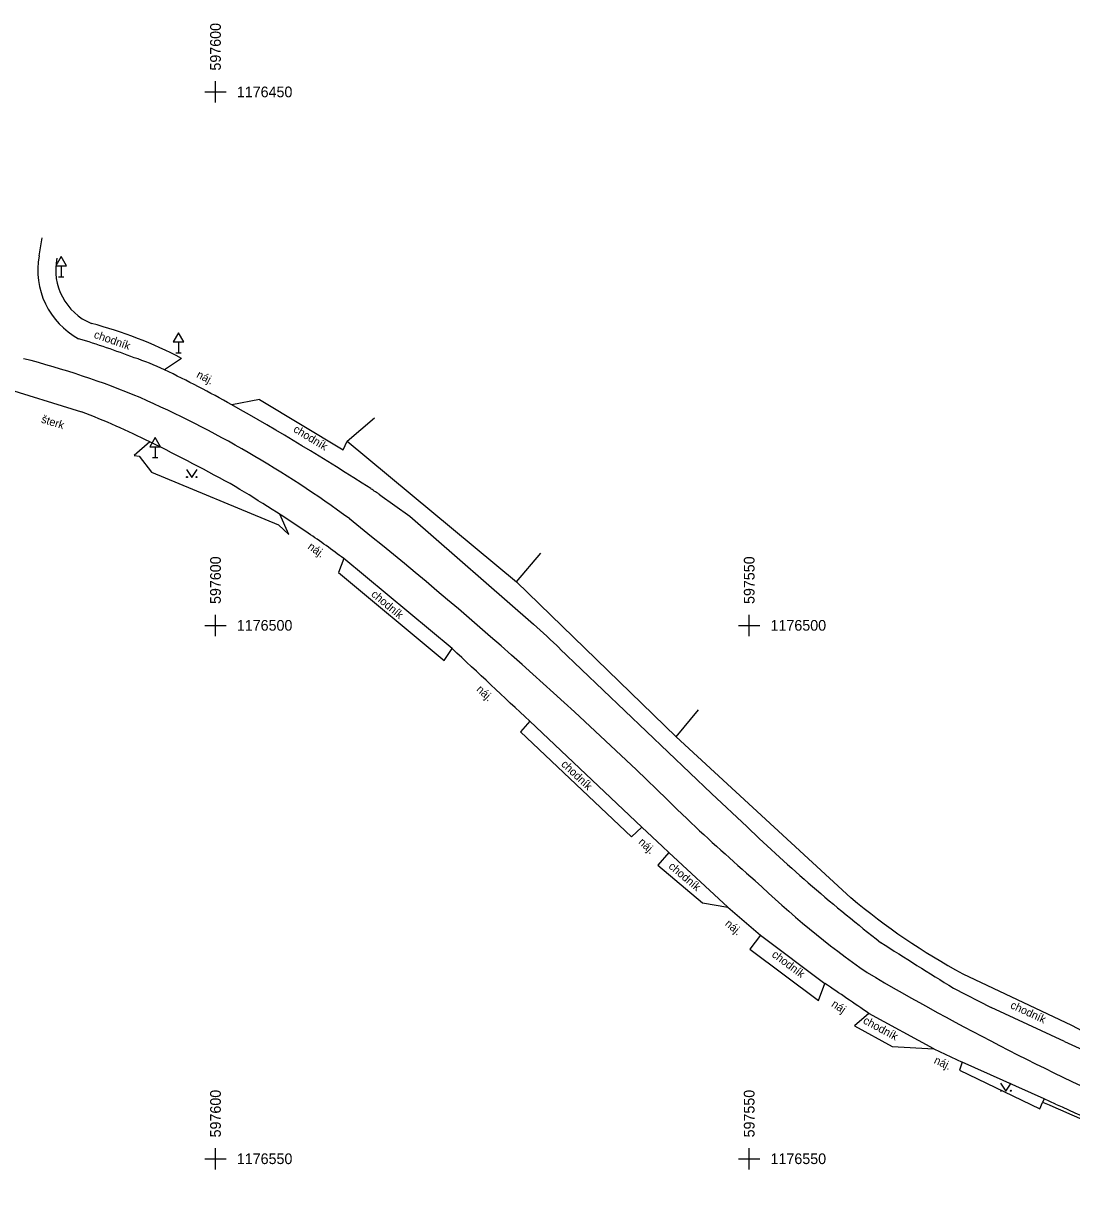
# Model space of a CAD drawing. Extents: x -598160 to -596067, y -1177005 to -1176344.
# Drawn here: x -597618 to -597519.8, y -1176553.9 to -1176443.6 of the extents above; entities that cross this region are included whole.
import ezdxf

# ---------------------------------------------------------------- set-up
doc = ezdxf.new("R2010")
doc.units = 0
for name, color, linetype in [('budova', 7, 'Continuous'), ('dopravní značení svislé', 7, 'Continuous'), ('hektametrová síť', 7, 'Continuous'), ('obruba +0 cm', 7, 'Continuous'), ('obruba +12 cm', 7, 'Continuous'), ('obruba +3 cm', 7, 'Continuous'), ('obruba +7 cm', 7, 'Continuous'), ('ohradní zeď', 7, 'Continuous'), ('plot', 7, 'Continuous'), ('popis ploch', 7, 'Continuous'), ('rozhraní ploch', 7, 'Continuous'), ('vodorovné značení', 7, 'Continuous'), ('zeleň', 7, 'Continuous')]:
    doc.layers.add(name, color=color, linetype=linetype)

msp = doc.modelspace()

# ---------------------------------------------------------------- linework, layer by layer
at = {"layer": 'budova'}
for p, q in [((-597587.65, -1176482.73), (-597585.09, -1176480.55)), ((-597587.65, -1176482.73), (-597571.8, -1176495.92)), ((-597571.8, -1176495.92), (-597569.52, -1176493.23)), ((-597571.8, -1176495.92), (-597556.83, -1176510.46)), ((-597556.83, -1176510.46), (-597554.74, -1176507.93))]:
    msp.add_line(p, q, dxfattribs=at)
at = {"layer": 'dopravní značení svislé'}
for p, q in [((-597614.45, -1176466.31), (-597614.45, -1176467.32)), ((-597614.7, -1176467.32), (-597614.2, -1176467.32)), ((-597603.72, -1176474.45), (-597603.22, -1176474.45)), ((-597603.47, -1176473.44), (-597603.47, -1176474.45)), ((-597605.64, -1176483.26), (-597605.64, -1176484.27)), ((-597605.89, -1176484.27), (-597605.39, -1176484.27))]:
    msp.add_line(p, q, dxfattribs=at)
for points in [[(-597614.95, -1176466.31), (-597613.95, -1176466.31), (-597614.45, -1176465.44)], [(-597603.97, -1176473.44), (-597602.97, -1176473.44), (-597603.47, -1176472.57)], [(-597606.14, -1176483.26), (-597605.14, -1176483.26), (-597605.64, -1176482.39)]]:
    msp.add_lwpolyline(points, close=True, dxfattribs=at)
at = {"layer": 'hektametrová síť'}
for p, q in [((-597600, -1176451), (-597600, -1176449)), ((-597601, -1176450), (-597599, -1176450)), ((-597600, -1176501), (-597600, -1176499)), ((-597550, -1176501), (-597550, -1176499)), ((-597601, -1176500), (-597599, -1176500)), ((-597551, -1176500), (-597549, -1176500)), ((-597600, -1176551), (-597600, -1176549)), ((-597550, -1176551), (-597550, -1176549)), ((-597601, -1176550), (-597599, -1176550)), ((-597551, -1176550), (-597549, -1176550))]:
    msp.add_line(p, q, dxfattribs=at)
at = {"layer": 'obruba +0 cm'}
for p, q in [((-597584.59, -1176487.76), (-597581.78, -1176489.77)), ((-597552.01, -1176526.42), (-597548.94, -1176529.05)), ((-597530.87, -1176534), (-597527.34, -1176535.81)), ((-597532.7, -1176539.69), (-597530.05, -1176540.95))]:
    msp.add_line(p, q, dxfattribs=at)
for centre, radius, start, end in [((-597660.89, -1176591.52), 128.39, 60.9119, 64.082), ((-597627.7, -1176545.57), 65.29, 52.5335, 56.1311), ((-597648.28, -1176586.93), 116.92, 46.4539, 48.1081), ((-597904.66, -1177067.79), 645.18, 55.45234, 55.89646), ((-597242.16, -1175937.85), 662.45, 245.15933, 245.4221)]:
    msp.add_arc(centre, radius, start, end, dxfattribs=at)
at = {"layer": 'obruba +12 cm'}
for p, q in [((-597616.51, -1176465.36), (-597616.25, -1176463.68)), ((-597577.83, -1176502.17), (-597587.98, -1176493.75)), ((-597570.56, -1176508.98), (-597560.06, -1176518.93)), ((-597557.52, -1176521.29), (-597552.01, -1176526.42)), ((-597548.94, -1176529.05), (-597542.92, -1176533.57)), ((-597520.45, -1176539.01), (-597527.34, -1176535.81)), ((-597532.7, -1176539.69), (-597538.79, -1176536.39)), ((-597522.38, -1176544.37), (-597530.05, -1176540.95)), ((-597521.29, -1176544.87), (-597522.38, -1176544.37))]:
    msp.add_line(p, q, dxfattribs=at)
for centre, radius, start, end in [((-597609.36, -1176466.73), 7.28, 169.1666, 241.6399), ((-597639.29, -1176558.95), 89.81, 69.3501, 72.857), ((-597615.72, -1176499.5), 25.89, 64.9776, 71.7667), ((-597637.42, -1176544.87), 69.49, 63.2593, 69.0318), ((-597736.09, -1176721.89), 278.89, 57.3045, 60.4323), ((-597687.62, -1176648.49), 184.63, 61.0122, 63.8136), ((-597673.07, -1176611.79), 145.56, 55.8283, 59.0236), ((-597669.94, -1176614.12), 152.48, 55.9624, 56.3461), ((-597439.97, -1176404.2), 159.07, 226.1417, 232.0993), ((-597282.83, -1176131.78), 472.55, 237.3635, 238.3388), ((-595960.58, -1173088.91), 3792.03, 245.69611, 246.01452)]:
    msp.add_arc(centre, radius, start, end, dxfattribs=at)
at = {"layer": 'obruba +3 cm'}
for p, q in [((-597620.23, -1176477.61), (-597612.55, -1176479.98)), ((-597553.53, -1176515.77), (-597550.18, -1176518.9)), ((-597560.06, -1176518.93), (-597558.13, -1176520.73)), ((-597558.13, -1176520.73), (-597557.52, -1176521.29))]:
    msp.add_line(p, q, dxfattribs=at)
msp.add_arc((-657799.42, -1240798.88), 88094.87, 46.8679742, 46.874453, dxfattribs=at)
at = {"layer": 'obruba +7 cm'}
for p, q in [((-597581.78, -1176489.77), (-597570.21, -1176499.9)), ((-597567.73, -1176502.19), (-597553.53, -1176515.77))]:
    msp.add_line(p, q, dxfattribs=at)
at = {"layer": 'ohradní zeď'}
msp.add_line((-597522.78, -1176545.31), (-597522.51, -1176544.72), dxfattribs=at)
msp.add_line((-597522.78, -1176545.31), (-597522.51, -1176544.72), dxfattribs=at)
msp.add_arc((-597741.74, -1177054.96), 555.35, 64.4531, 66.7485, dxfattribs=at)
at = {"layer": 'plot'}
msp.add_line((-597519.81, -1176537.49), (-597510, -1176542.72), dxfattribs=at)
at = {"layer": 'rozhraní ploch'}
for p, q in [((-597603.18, -1176474.98), (-597604.77, -1176476.04)), ((-597595.89, -1176478.83), (-597598.47, -1176479.32)), ((-597595.89, -1176478.83), (-597588.05, -1176483.56)), ((-597606.15, -1176482.81), (-597607.62, -1176484.09)), ((-597588.05, -1176483.56), (-597587.65, -1176482.73)), ((-597607.62, -1176484.09), (-597607.14, -1176484.15)), ((-597607.14, -1176484.15), (-597605.98, -1176485.65)), ((-597605.98, -1176485.65), (-597594.09, -1176490.57)), ((-597593.14, -1176491.47), (-597593.98, -1176489.59)), ((-597594.09, -1176490.57), (-597593.14, -1176491.47)), ((-597587.98, -1176493.75), (-597588.46, -1176495.04)), ((-597588.46, -1176495.04), (-597578.57, -1176503.31)), ((-597578.57, -1176503.31), (-597577.83, -1176502.17)), ((-597570.56, -1176508.98), (-597571.44, -1176509.99)), ((-597571.44, -1176509.99), (-597561.03, -1176519.84)), ((-597556.83, -1176510.46), (-597540.47, -1176525.53)), ((-597561.03, -1176519.84), (-597560.06, -1176518.93)), ((-597557.52, -1176521.29), (-597558.55, -1176522.47)), ((-597558.55, -1176522.47), (-597554.36, -1176526.02)), ((-597554.36, -1176526.02), (-597552.01, -1176526.42)), ((-597548.94, -1176529.05), (-597549.95, -1176530.37)), ((-597549.95, -1176530.37), (-597543.51, -1176535.18)), ((-597529.99, -1176532.67), (-597519.81, -1176537.49)), ((-597543.51, -1176535.18), (-597542.92, -1176533.57)), ((-597538.79, -1176536.39), (-597540.13, -1176537.55)), ((-597540.13, -1176537.55), (-597536.6, -1176539.47)), ((-597536.6, -1176539.47), (-597532.7, -1176539.69)), ((-597530.05, -1176540.95), (-597530.31, -1176541.71)), ((-597530.31, -1176541.71), (-597522.78, -1176545.31)), ((-597522.38, -1176544.37), (-597522.51, -1176544.72))]:
    msp.add_line(p, q, dxfattribs=at)
for centre, radius, start, end in [((-597609.51, -1176466.67), 5.46, 168.5612, 247.1644), ((-597622.23, -1176511.54), 41.23, 62.4741, 75.0969), ((-597499.65, -1176476.87), 63.51, 230.0039, 241.4631)]:
    msp.add_arc(centre, radius, start, end, dxfattribs=at)
at = {"layer": 'vodorovné značení'}
for centre, radius, start, end in [((-597637.16, -1176550.56), 77.95, 67.2825, 75.7532), ((-597648.7, -1176573.18), 103.29, 53.6153, 66.2245), ((-597847.66, -1176814.38), 415.84, 45.4281, 51.2599), ((-597397.37, -1176349.7), 231.26, 226.7519, 228.8837), ((-597488.4, -1176460.4), 88.1, 226.1557, 234.98), ((-597409.37, -1176311.99), 255.81, 239.5638, 246.3401)]:
    msp.add_arc(centre, radius, start, end, dxfattribs=at)
at = {"layer": 'zeleň'}
for points in [[(-597602.72, -1176485.4), (-597602.22, -1176486.15), (-597601.72, -1176485.4)], [(-597526.45, -1176542.93), (-597525.95, -1176543.68), (-597525.45, -1176542.93)]]:
    msp.add_lwpolyline(points, dxfattribs=at)
for centre in [(-597602.67, -1176486.1), (-597601.77, -1176486.1), (-597526.4, -1176543.63), (-597525.5, -1176543.63)]:
    msp.add_circle(centre, 0.05, dxfattribs=at)

# ---------------------------------------------------------------- texts
at = {"layer": 'hektametrová síť'}
for s, p in [('597600', (-597599.5, -1176448)), ('597600', (-597599.5, -1176498)), ('597550', (-597549.5, -1176498)), ('597600', (-597599.5, -1176548)), ('597550', (-597549.5, -1176548))]:
    msp.add_text(s, height=1, rotation=90, dxfattribs=at).set_placement(p)
for s, p in [('1176450', (-597598, -1176450.5)), ('1176500', (-597598, -1176500.5)), ('1176500', (-597548, -1176500.5)), ('1176550', (-597598, -1176550.5)), ('1176550', (-597548, -1176550.5))]:
    msp.add_text(s, height=1, dxfattribs=at).set_placement(p)
at = {"layer": 'popis ploch'}
for s, rotation, p in [('chodník', 340.7339, (-597611.45, -1176473.03)), ('náj.', 332.3135, (-597601.84, -1176476.72)), ('šterk', 342.8501, (-597616.38, -1176480.98)), ('chodník', 328.6935, (-597592.78, -1176481.81)), ('náj.', 324.7007, (-597591.42, -1176492.77)), ('chodník', 320.0977, (-597585.48, -1176497.19)), ('náj.', 316.8714, (-597575.61, -1176506.08)), ('chodník', 316.5833, (-597567.68, -1176513.09)), ('náj.', 316.9961, (-597560.43, -1176520.39)), ('chodník', 319.7269, (-597557.62, -1176522.69)), ('náj.', 319.4141, (-597552.32, -1176528.06)), ('chodník', 323.2442, (-597547.95, -1176530.99)), ('náj', 325.6913, (-597542.36, -1176535.66)), ('chodník', 335.0879, (-597525.6, -1176535.85)), ('chodník', 331.4578, (-597539.4, -1176537.26)), ('náj.', 334.5702, (-597532.75, -1176541.01))]:
    msp.add_text(s, height=0.75, rotation=rotation, dxfattribs=at).set_placement(p)

doc.saveas('drawing.dxf')
